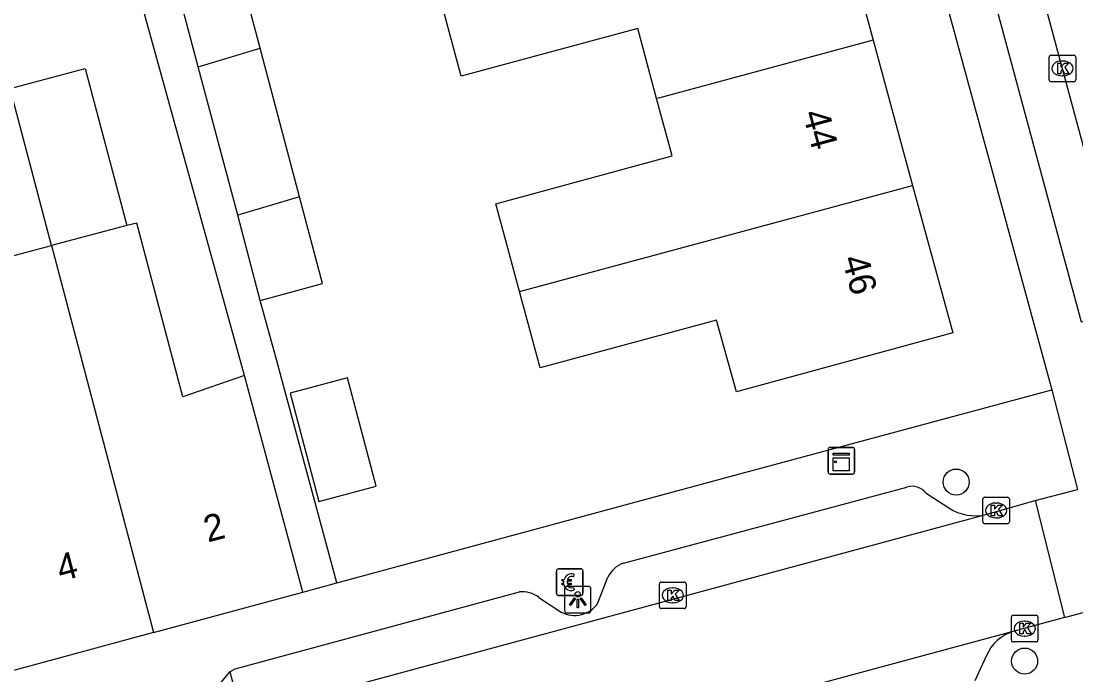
# Model space of a CAD drawing. Extents: x 159265 to 160143, y 383413 to 384319.
# Drawn here: x 159771.66 to 159811.32, y 383815.57 to 383840.14 of the extents above; entities that cross this region are included whole.
import ezdxf

# ---------------------------------------------------------------- set-up
doc = ezdxf.new("R2010")
doc.units = 0
for name, color, linetype in [('IMGEO_Betaalautomaat', 7, 'Continuous'), ('IMGEO_Boom', 7, 'Continuous'), ('IMGEO_Kast', 7, 'Continuous'), ('IMGEO_Kolk', 7, 'Continuous'), ('IMGEO_Lichtpunt', 7, 'Continuous'), ('IMGEO_Pand', 7, 'Continuous'), ('IMGEO_Pand_nummerreeks', 7, 'Continuous'), ('IMGEO_Parkeervlak_open', 7, 'Continuous'), ('IMGEO_Rijbaan_lokaal_open', 7, 'Continuous'), ('IMGEO_Voetpad_open', 7, 'Continuous')]:
    doc.layers.add(name, color=color, linetype=linetype)

msp = doc.modelspace()

# ---------------------------------------------------------------- linework, layer by layer
at = {"layer": 'IMGEO_Betaalautomaat'}
for p, q in [((159791.785, 383818.631), (159791.785, 383819.472)), ((159791.785, 383819.472), (159791.785, 383818.631)), ((159791.86, 383819.555), (159792.701, 383819.555)), ((159792.701, 383819.555), (159791.86, 383819.555)), ((159792.447, 383819.36), (159792.43, 383819.26)), ((159792.784, 383819.481), (159792.784, 383818.64)), ((159792.784, 383818.64), (159792.784, 383819.481)), ((159792.068, 383819.019), (159792.068, 383819.087)), ((159792.189, 383819.087), (159792.189, 383819.019)), ((159792.434, 383818.854), (159792.456, 383818.767)), ((159792.71, 383818.556), (159791.869, 383818.556)), ((159791.869, 383818.556), (159792.71, 383818.556))]:
    msp.add_line(p, q, dxfattribs=at)
for points in [[(159792.068, 383819.087), (159791.999, 383819.087), (159791.999, 383819.156), (159792.078, 383819.156)], [(159792.073, 383818.95), (159791.999, 383818.95), (159791.999, 383819.019), (159792.068, 383819.019)], [(159792.2, 383819.156), (159792.347, 383819.156), (159792.347, 383819.087), (159792.189, 383819.087)], [(159792.189, 383819.019), (159792.347, 383819.019), (159792.347, 383818.95), (159792.203, 383818.95)]]:
    msp.add_lwpolyline(points, dxfattribs=at)
for centre, radius, start, end in [((159791.863, 383819.478), 0.0779, 92.4484, 184.2845), ((159791.863, 383819.478), 0.0779, 92.4484, 184.2845), ((159792.361, 383819.08), 0.293, 73.014, 165.0139), ((159792.707, 383819.478), 0.0779, 2.4484, 94.2845), ((159792.707, 383819.478), 0.0779, 2.4484, 94.2845), ((159792.367, 383819.093), 0.179, 69.3236, 159.5683), ((159791.863, 383818.634), 0.0779, 182.4484, 274.2845), ((159791.863, 383818.634), 0.0779, 182.4484, 274.2845), ((159792.334, 383819.005), 0.267, 191.8096, 297.0389), ((159792.367, 383819.02), 0.179, 202.7625, 291.8693), ((159792.707, 383818.634), 0.0779, 272.4484, 4.2845), ((159792.707, 383818.634), 0.0779, 272.4484, 4.2845)]:
    msp.add_arc(centre, radius, start, end, dxfattribs=at)
at = {"layer": 'IMGEO_Boom'}
for centre in [(159806.814, 383822.819), (159809.388, 383816.09)]:
    msp.add_circle(centre, 0.489, dxfattribs=at)
at = {"layer": 'IMGEO_Kast'}
for p, q in [((159801.997, 383823.193), (159801.997, 383824.034)), ((159801.997, 383824.034), (159801.997, 383823.193)), ((159802.072, 383824.118), (159802.913, 383824.118)), ((159802.913, 383824.118), (159802.072, 383824.118)), ((159802.997, 383824.043), (159802.997, 383823.202)), ((159802.997, 383823.202), (159802.997, 383824.043)), ((159802.922, 383823.118), (159802.081, 383823.118)), ((159802.081, 383823.118), (159802.922, 383823.118))]:
    msp.add_line(p, q, dxfattribs=at)
for points in [[(159802.192, 383823.908), (159802.792, 383823.908), (159802.792, 383823.823), (159802.192, 383823.823), (159802.192, 383823.908)], [(159802.192, 383823.733), (159802.792, 383823.733), (159802.792, 383823.244), (159802.192, 383823.244), (159802.192, 383823.733)]]:
    msp.add_lwpolyline(points, dxfattribs=at)
msp.add_circle((159802.276, 383823.582), 0.0377, dxfattribs=at)
for centre, start, end in [((159802.075, 383824.04), 92.4484, 184.2845), ((159802.075, 383824.04), 92.4484, 184.2845), ((159802.919, 383824.04), 2.4484, 94.2845), ((159802.919, 383824.04), 2.4484, 94.2845), ((159802.075, 383823.196), 182.4484, 274.2845), ((159802.075, 383823.196), 182.4484, 274.2845), ((159802.919, 383823.196), 272.4484, 4.2845), ((159802.919, 383823.196), 272.4484, 4.2845)]:
    msp.add_arc(centre, 0.0779, start, end, dxfattribs=at)
at = {"layer": 'IMGEO_Kolk'}
for p, q in [((159810.384, 383838.861), (159811.236, 383838.861)), ((159810.309, 383837.935), (159810.309, 383838.787)), ((159810.797, 383838.641), (159810.822, 383838.641)), ((159811.31, 383838.787), (159811.31, 383837.935)), ((159810.82, 383838.081), (159810.795, 383838.081)), ((159811.236, 383837.861), (159810.384, 383837.861)), ((159807.815, 383821.323), (159807.815, 383822.175)), ((159807.89, 383822.249), (159808.742, 383822.249)), ((159808.816, 383822.175), (159808.816, 383821.323)), ((159808.303, 383822.029), (159808.328, 383822.029)), ((159808.326, 383821.469), (159808.301, 383821.469)), ((159808.742, 383821.249), (159807.89, 383821.249)), ((159795.66, 383818.135), (159795.66, 383818.987)), ((159795.735, 383819.061), (159796.587, 383819.061)), ((159796.661, 383818.987), (159796.661, 383818.135)), ((159796.148, 383818.841), (159796.173, 383818.841)), ((159796.171, 383818.281), (159796.146, 383818.281)), ((159796.587, 383818.061), (159795.735, 383818.061)), ((159808.964, 383817.81), (159809.816, 383817.81)), ((159808.889, 383816.884), (159808.889, 383817.736)), ((159809.377, 383817.59), (159809.402, 383817.59)), ((159809.89, 383817.736), (159809.89, 383816.884)), ((159809.4, 383817.03), (159809.375, 383817.03)), ((159809.816, 383816.81), (159808.964, 383816.81))]:
    msp.add_line(p, q, dxfattribs=at)
for points in [[(159810.384, 383838.861), (159811.236, 383838.861)], [(159810.309, 383837.935), (159810.309, 383838.787)], [(159810.63, 383838.561), (159810.753, 383838.561), (159810.753, 383838.41), (159810.883, 383838.561), (159811.047, 383838.561), (159810.901, 383838.41), (159811.054, 383838.161), (159810.902, 383838.161), (159810.817, 383838.325), (159810.753, 383838.258), (159810.753, 383838.161), (159810.63, 383838.161), (159810.63, 383838.561)], [(159811.31, 383838.787), (159811.31, 383837.935)], [(159811.236, 383837.861), (159810.384, 383837.861)], [(159807.815, 383821.323), (159807.815, 383822.175)], [(159807.89, 383822.249), (159808.742, 383822.249)], [(159808.816, 383822.175), (159808.816, 383821.323)], [(159808.136, 383821.949), (159808.259, 383821.949), (159808.259, 383821.798), (159808.389, 383821.949), (159808.553, 383821.949), (159808.407, 383821.798), (159808.56, 383821.549), (159808.408, 383821.549), (159808.323, 383821.713), (159808.259, 383821.646), (159808.259, 383821.549), (159808.136, 383821.549), (159808.136, 383821.949)], [(159808.742, 383821.249), (159807.89, 383821.249)], [(159795.66, 383818.135), (159795.66, 383818.987)], [(159795.735, 383819.061), (159796.587, 383819.061)], [(159796.661, 383818.987), (159796.661, 383818.135)], [(159795.981, 383818.761), (159796.104, 383818.761), (159796.104, 383818.61), (159796.234, 383818.761), (159796.398, 383818.761), (159796.252, 383818.61), (159796.405, 383818.361), (159796.253, 383818.361), (159796.168, 383818.525), (159796.104, 383818.458), (159796.104, 383818.361), (159795.981, 383818.361), (159795.981, 383818.761)], [(159796.587, 383818.061), (159795.735, 383818.061)], [(159808.964, 383817.81), (159809.816, 383817.81)], [(159808.889, 383816.884), (159808.889, 383817.736)], [(159809.21, 383817.51), (159809.333, 383817.51), (159809.333, 383817.359), (159809.463, 383817.51), (159809.627, 383817.51), (159809.481, 383817.359), (159809.634, 383817.11), (159809.482, 383817.11), (159809.397, 383817.274), (159809.333, 383817.207), (159809.333, 383817.11), (159809.21, 383817.11), (159809.21, 383817.51)], [(159809.89, 383817.736), (159809.89, 383816.884)], [(159809.816, 383816.81), (159808.964, 383816.81)]]:
    msp.add_lwpolyline(points, dxfattribs=at)
for centre, start, end in [((159810.386, 383838.785), 91.552, 178.448), ((159810.386, 383838.785), 91.552, 178.448), ((159811.234, 383838.785), 1.552, 88.448), ((159811.234, 383838.785), 1.552, 88.448), ((159810.386, 383837.937), 181.552, 268.448), ((159810.386, 383837.937), 181.552, 268.448), ((159811.234, 383837.937), 271.552, 358.448), ((159811.234, 383837.937), 271.552, 358.448), ((159807.892, 383822.173), 91.552, 178.448), ((159807.892, 383822.173), 91.552, 178.448), ((159808.74, 383822.173), 1.552, 88.448), ((159808.74, 383822.173), 1.552, 88.448), ((159807.892, 383821.325), 181.552, 268.448), ((159807.892, 383821.325), 181.552, 268.448), ((159808.74, 383821.325), 271.552, 358.448), ((159808.74, 383821.325), 271.552, 358.448), ((159795.737, 383818.985), 91.552, 178.448), ((159795.737, 383818.985), 91.552, 178.448), ((159796.585, 383818.985), 1.552, 88.448), ((159796.585, 383818.985), 1.552, 88.448), ((159795.737, 383818.137), 181.552, 268.448), ((159795.737, 383818.137), 181.552, 268.448), ((159796.585, 383818.137), 271.552, 358.448), ((159796.585, 383818.137), 271.552, 358.448), ((159808.966, 383817.734), 91.552, 178.448), ((159808.966, 383817.734), 91.552, 178.448), ((159809.814, 383817.734), 1.552, 88.448), ((159809.814, 383817.734), 1.552, 88.448), ((159808.966, 383816.886), 181.552, 268.448), ((159808.966, 383816.886), 181.552, 268.448), ((159809.814, 383816.886), 271.552, 358.448), ((159809.814, 383816.886), 271.552, 358.448)]:
    msp.add_arc(centre, 0.0765, start, end, dxfattribs=at)
for centre, major_axis, ratio, start_param, end_param in [((159810.796, 383838.361), (-0.387, 0.002), 0.722429, 4.712389, 7.853982), ((159810.821, 383838.361), (-0.39, 0.002), 0.717154, 1.570796, 4.712389), ((159808.302, 383821.749), (-0.387, 0.002), 0.722429, 4.712389, 7.853982), ((159808.327, 383821.749), (-0.39, 0.002), 0.717154, 1.570796, 4.712389), ((159796.147, 383818.561), (-0.387, 0.002), 0.722429, 4.712389, 7.853982), ((159796.172, 383818.561), (-0.39, 0.002), 0.717154, 1.570796, 4.712389), ((159809.376, 383817.31), (-0.387, 0.002), 0.722429, 4.712389, 7.853982), ((159809.401, 383817.31), (-0.39, 0.002), 0.717154, 1.570796, 4.712389)]:
    msp.add_ellipse(centre, major_axis=major_axis, ratio=ratio, start_param=start_param, end_param=end_param, dxfattribs=at)
at = {"layer": 'IMGEO_Lichtpunt'}
for p, q in [((159792.091, 383818.803), (159792.091, 383817.996)), ((159792.091, 383818.803), (159792.091, 383817.996)), ((159792.993, 383818.898), (159792.185, 383818.898)), ((159792.993, 383818.898), (159792.185, 383818.898)), ((159793.087, 383817.996), (159793.087, 383818.803)), ((159793.087, 383817.996), (159793.087, 383818.803)), ((159792.185, 383817.902), (159792.993, 383817.902)), ((159792.185, 383817.902), (159792.993, 383817.902))]:
    msp.add_line(p, q, dxfattribs=at)
for points in [[(159792.465, 383818.467), (159792.504, 383818.439), (159792.316, 383818.177), (159792.278, 383818.204), (159792.465, 383818.467)], [(159792.567, 383818.419), (159792.614, 383818.419), (159792.614, 383818.097), (159792.567, 383818.097), (159792.567, 383818.419)], [(159792.677, 383818.439), (159792.715, 383818.466), (159792.902, 383818.204), (159792.863, 383818.176), (159792.677, 383818.439)]]:
    msp.add_lwpolyline(points, dxfattribs=at)
msp.add_circle((159792.59, 383818.601), 0.0994, dxfattribs=at)
for centre, start, end in [((159792.185, 383818.803), 90, 180), ((159792.185, 383818.803), 90, 180), ((159792.993, 383818.803), 0, 90), ((159792.993, 383818.803), 0, 90), ((159792.185, 383817.996), 180, 270), ((159792.185, 383817.996), 180, 270), ((159792.993, 383817.996), 270, 0), ((159792.993, 383817.996), 270, 360)]:
    msp.add_arc(centre, 0.0946, start, end, dxfattribs=at)
at = {"layer": 'IMGEO_Pand'}
for points in [[(159802.214, 383844.891), (159803.693, 383839.425)], [(159780.648, 383839.118), (159779.18, 383844.649), (159776.858, 383843.958)], [(159778.325, 383838.427), (159776.858, 383843.958)], [(159795.555, 383837.231), (159794.844, 383839.859), (159788.212, 383838.065), (159787.443, 383840.91)], [(159803.693, 383839.425), (159795.673, 383837.263), (159795.555, 383837.231)], [(159803.693, 383839.425), (159805.171, 383833.96)], [(159778.325, 383838.427), (159780.648, 383839.118)], [(159782.129, 383833.534), (159780.648, 383839.118)], [(159779.807, 383832.844), (159778.325, 383838.427)], [(159772.809, 383831.702), (159771.253, 383837.61), (159774.075, 383838.359), (159775.641, 383832.453)], [(159790.399, 383829.977), (159789.87, 383831.935), (159789.507, 383833.277), (159796.139, 383835.071), (159795.555, 383837.231)], [(159805.171, 383833.96), (159806.695, 383828.427), (159798.556, 383826.211), (159797.807, 383828.902), (159791.175, 383827.108), (159790.399, 383829.977)], [(159790.399, 383829.977), (159805.171, 383833.96)], [(159782.129, 383833.534), (159779.807, 383832.844)], [(159780.656, 383829.644), (159782.994, 383830.275), (159782.129, 383833.534)], [(159780.656, 383829.644), (159779.807, 383832.844)], [(159775.641, 383832.453), (159772.809, 383831.702)], [(159780.061, 383826.825), (159777.749, 383826.021), (159776.017, 383832.553), (159775.641, 383832.453)], [(159769.021, 383823.759), (159771.32, 383824.37), (159769.601, 383830.851), (159772.809, 383831.702)], [(159772.809, 383831.702), (159776.639, 383817.16)], [(159782.255, 383818.684), (159780.061, 383826.825)], [(159781.777, 383826.162), (159782.859, 383822.086), (159785.016, 383822.658), (159783.934, 383826.735), (159781.777, 383826.162)], [(159776.639, 383817.16), (159782.255, 383818.684)], [(159776.639, 383817.16), (159771.151, 383815.672)]]:
    msp.add_lwpolyline(points, dxfattribs=at)
at = {"layer": 'IMGEO_Parkeervlak_open'}
msp.add_lwpolyline([(159779.514, 383815.681), (159779.954, 383814.038)], dxfattribs=at)
at = {"layer": 'IMGEO_Rijbaan_lokaal_open'}
for points in [[(159813.268, 383829.254), (159805.711, 383857.248)], [(159809.783, 383822.128), (159811.373, 383822.538)], [(159807.933, 383821.6), (159809.783, 383822.128)], [(159809.783, 383822.128), (159810.888, 383817.723)], [(159779.954, 383814.038), (159807.933, 383821.6)], [(159810.888, 383817.723), (159812.514, 383818.172)], [(159810.888, 383817.723), (159808.996, 383817.216)], [(159808.996, 383817.216), (159781.118, 383809.691)]]:
    msp.add_lwpolyline(points, dxfattribs=at)
at = {"layer": 'IMGEO_Voetpad_open'}
for points in [[(159800.596, 383862.326), (159805.418, 383844.577), (159810.41, 383826.285)], [(159813.268, 383829.254), (159811.53, 383828.823), (159803.983, 383856.776), (159805.711, 383857.248)], [(159780.061, 383826.825), (159773.045, 383852.196)], [(159783.539, 383819.032), (159781.244, 383827.509), (159780.656, 383829.644)], [(159783.539, 383819.032), (159798.168, 383822.992), (159810.41, 383826.285)], [(159810.41, 383826.285), (159811.373, 383822.538)], [(159794.306, 383819.764), (159804.957, 383822.627)], [(159805.684, 383822.406), (159806.541, 383821.844)], [(159782.255, 383818.684), (159783.539, 383819.032)], [(159793.35, 383818.276), (159793.726, 383819.241)], [(159779.514, 383815.681), (159779.716, 383815.804), (159790.394, 383818.691)], [(159791.129, 383818.484), (159791.967, 383817.93)], [(159807.947, 383816.275), (159807.517, 383815.352)], [(159778.744, 383814.392), (159779.177, 383815.27), (159779.514, 383815.681)]]:
    msp.add_lwpolyline(points, dxfattribs=at)
for centre, radius, start, end in [((159805.159, 383821.986), 0.672, 38.6735, 107.5091), ((159807.521, 383823.344), 1.792, 236.8387, 283.2768), ((159794.618, 383818.834), 0.981, 108.578, 155.5055), ((159790.49, 383817.623), 1.072, 53.417, 95.125), ((159792.467, 383818.869), 1.064, 241.9671, 326.1249), ((159809.425, 383815.682), 1.593, 105.6413, 158.1458)]:
    msp.add_arc(centre, radius, start, end, dxfattribs=at)

# ---------------------------------------------------------------- texts
at = {"layer": 'IMGEO_Pand_nummerreeks'}
for s, rotation, p in [('44', 285.1214, (159801.034, 383836.675)), ('46', 285.1938, (159802.513, 383831.208)), ('2', 14.8568, (159778.683, 383820.543)), ('4', 14.8581, (159773.153, 383819.077))]:
    msp.add_text(s, height=1, rotation=rotation, dxfattribs=at).set_placement(p)

doc.saveas('drawing.dxf')
